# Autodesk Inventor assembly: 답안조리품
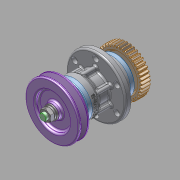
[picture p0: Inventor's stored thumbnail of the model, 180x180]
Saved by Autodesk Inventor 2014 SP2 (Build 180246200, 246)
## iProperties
Created: 2024-04
Part Number: 답안조리품
Document SubType Name: Assembly
Designer: Administrator
Author: Administrator
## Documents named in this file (14)
- C:\Users\Administrator\Desktop\740404V1007\답안조리품.iam
- C:\Users\Administrator\Desktop\740404V1007\본체.ipt
- C:\Users\Administrator\Desktop\740404V1007\가져온 구성요소\깊은 홈 볼 베어링 6204\깊은 홈 볼 베어링 6204.ipt
- C:\Users\Administrator\Desktop\740404V1007\가져온 구성요소\축\축.ipt
- C:\Users\Administrator\Desktop\740404V1007\가져온 구성요소\커버\커버.ipt
- C:\Users\Administrator\Desktop\740404V1007\가져온 구성요소\육각 소켓 머리 볼트 M4x10\육각 소켓 머리 볼트 M4x10.ipt
- C:\Users\Administrator\Desktop\740404V1007\가져온 구성요소\오일 실 20 32 5\오일 실 20 32 5.ipt
- C:\Users\Administrator\Desktop\740404V1007\가져온 구성요소\평행키 4x4x12\평행키 4x4x12.ipt
- C:\Users\Administrator\Desktop\740404V1007\가져온 구성요소\평행키 4x4x18\평행키 4x4x18.ipt
- C:\Users\Administrator\Desktop\740404V1007\가져온 구성요소\V-벨트풀리\V-벨트풀리.ipt
- C:\Users\Administrator\Desktop\740404V1007\가져온 구성요소\스퍼기어\스퍼기어.ipt
- C:\Users\Administrator\Desktop\740404V1007\가져온 구성요소\스프링와셔 M12\스프링와셔 M12.ipt
- C:\Users\Administrator\Desktop\740404V1007\가져온 구성요소\평와셔 M12\평와셔 M12.ipt
- C:\Users\Administrator\Desktop\740404V1007\가져온 구성요소\육각너트 M12x1\육각너트 M12x1.ipt
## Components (1 placed, 1 different names)
1. V-벨트풀리:1
